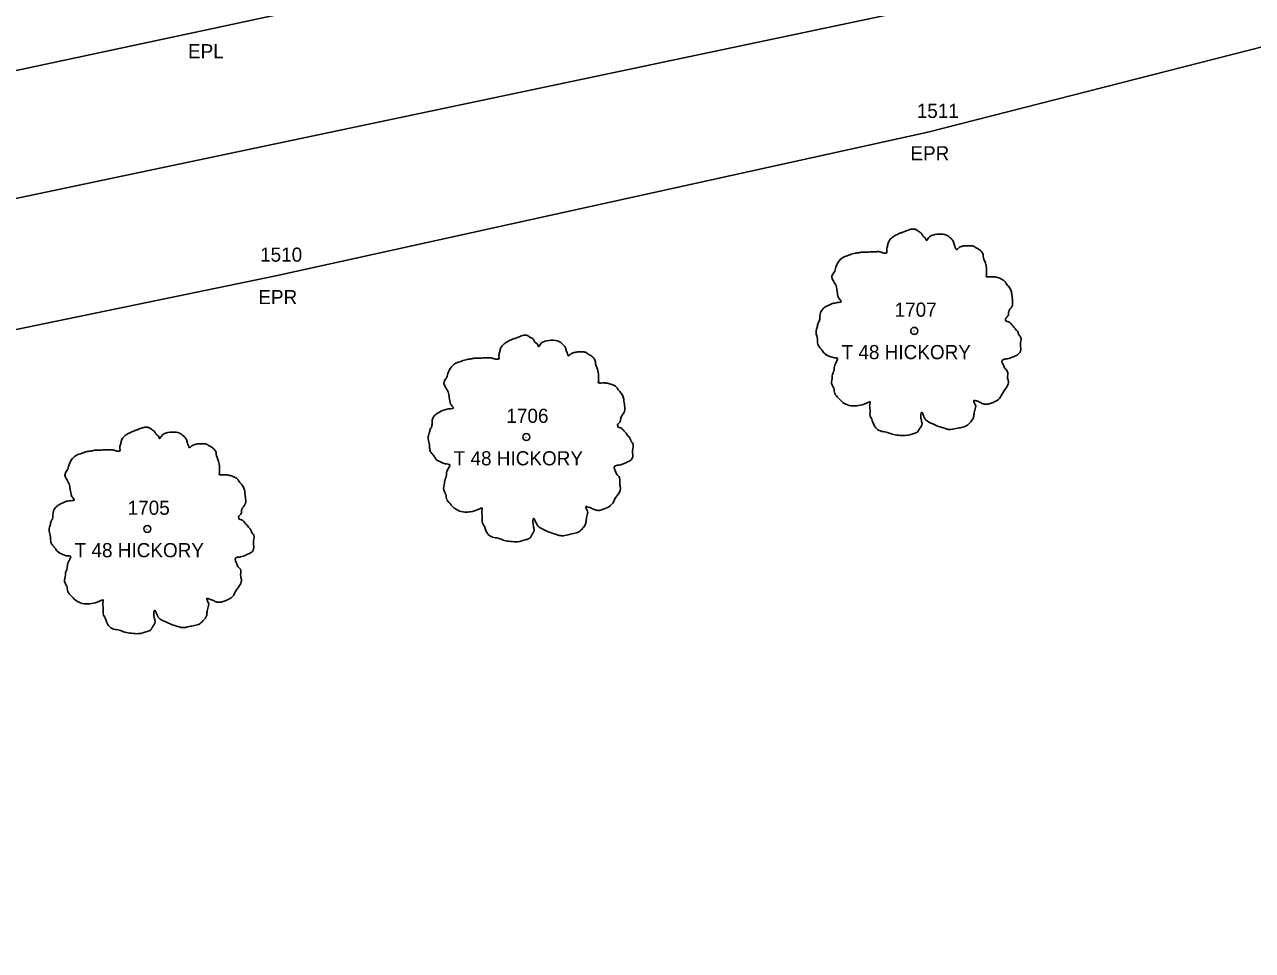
# Model space of a CAD drawing. Extents: x 1964982 to 1970452, y 1116335 to 1119906.
# Drawn here: x 1966611.8 to 1966698.6, y 1117353.3 to 1117418.7 of the extents above; entities that cross this region are included whole.
import ezdxf

# ---------------------------------------------------------------- set-up
doc = ezdxf.new("R2010")
doc.units = 0
for name, color, linetype in [('RD_EX_DV_Prop', 7, 'Continuous'), ('RD_EX_Road', 7, 'Continuous'), ('RD_EX_Road_txCode', 7, 'Continuous'), ('RD_EX_RW', 7, 'Continuous'), ('RD_EX_VEG', 7, 'Continuous'), ('RD_EX_VEG_txCode', 7, 'Continuous'), ('RD_HC_CL', 7, 'Continuous'), ('RD_SMD_Locator', 7, 'Continuous')]:
    doc.layers.add(name, color=color, linetype=linetype)

msp = doc.modelspace()

# ---------------------------------------------------------------- linework, layer by layer
at = {"layer": 'RD_EX_DV_Prop'}
msp.add_line((1966425.261, 1117367.215), (1966684.872, 1117421.945), dxfattribs=at)
at = {"layer": 'RD_EX_Road'}
for points in [[(1966484.547, 1117389.131), (1966531.199, 1117398.733), (1966578.388, 1117408.593), (1966604.527, 1117414.058), (1966624.537, 1117418.323), (1966671.319, 1117428.348), (1966716.506, 1117439.32), (1966736.604, 1117445.59), (1966754.133, 1117451.442), (1966759.658, 1117453.517), (1966769.512, 1117457.475)], [(1965729.992, 1117080.297), (1965819.77, 1117119.134), (1965907.737, 1117159.312), (1965995.365, 1117199.039), (1966039.268, 1117218.497), (1966081.241, 1117237.148), (1966124.665, 1117256.555), (1966167.659, 1117275.555), (1966211.467, 1117293.627), (1966257.791, 1117311.581), (1966302.7, 1117327.207), (1966347.903, 1117339.982), (1966394.806, 1117351.637), (1966441.557, 1117361.865), (1966488.625, 1117372.057), (1966534.906, 1117381.34), (1966581.234, 1117390.947), (1966629.533, 1117400.947), (1966675.632, 1117411.107), (1966721.676, 1117422.847), (1966766.802, 1117438.972), (1966775.751, 1117440.571)]]:
    msp.add_lwpolyline(points, dxfattribs=at)
at = {"layer": 'RD_EX_RW'}
for points in [[(1966484.547, 1117389.131), (1966531.199, 1117398.733), (1966578.388, 1117408.593), (1966604.527, 1117414.058), (1966624.537, 1117418.323), (1966671.319, 1117428.348), (1966716.506, 1117439.32), (1966736.604, 1117445.59), (1966754.133, 1117451.442), (1966759.658, 1117453.517), (1966769.512, 1117457.475)], [(1965729.992, 1117080.297), (1965819.77, 1117119.134), (1965907.737, 1117159.312), (1965995.365, 1117199.039), (1966039.268, 1117218.497), (1966081.241, 1117237.148), (1966124.665, 1117256.555), (1966167.659, 1117275.555), (1966211.467, 1117293.627), (1966257.791, 1117311.581), (1966302.7, 1117327.207), (1966347.903, 1117339.982), (1966394.806, 1117351.637), (1966441.557, 1117361.865), (1966488.625, 1117372.057), (1966534.906, 1117381.34), (1966581.234, 1117390.947), (1966629.533, 1117400.947), (1966675.632, 1117411.107), (1966721.676, 1117422.847), (1966766.802, 1117438.972), (1966775.751, 1117440.571)]]:
    msp.add_lwpolyline(points, dxfattribs=at)
at = {"layer": 'RD_EX_VEG'}
for centre, radius in [((1966674.675, 1117397.058), 0.25), ((1966674.662, 1117397.04), 0.0001), ((1966647.251, 1117389.554), 0.25), ((1966647.238, 1117389.535), 0.0001), ((1966620.454, 1117383.059), 0.25), ((1966620.441, 1117383.04), 0.0001)]:
    msp.add_circle(centre, radius, dxfattribs=at)
for points in [[(1966674.806, 1117404.226), (1966674.507, 1117404.251), (1966674.182, 1117404.151), (1966673.932, 1117404.051), (1966673.707, 1117403.976), (1966673.482, 1117403.876), (1966673.182, 1117403.701), (1966672.957, 1117403.501), (1966672.832, 1117403.251), (1966672.782, 1117403.026), (1966672.732, 1117402.751), (1966672.732, 1117402.576), (1966672.607, 1117402.551), (1966672.457, 1117402.576), (1966672.208, 1117402.651), (1966671.958, 1117402.651), (1966671.708, 1117402.651), (1966671.358, 1117402.626), (1966671.008, 1117402.626), (1966670.733, 1117402.576), (1966670.408, 1117402.526), (1966670.034, 1117402.401), (1966669.684, 1117402.276), (1966669.384, 1117402.027), (1966669.134, 1117401.552), (1966669.009, 1117401.202), (1966668.859, 1117400.952), (1966669.009, 1117400.502), (1966669.184, 1117400.152), (1966669.209, 1117399.952), (1966669.284, 1117399.528), (1966669.384, 1117399.303), (1966669.509, 1117399.103), (1966669.434, 1117399.078), (1966669.059, 1117399.028), (1966668.759, 1117398.928), (1966668.334, 1117398.703), (1966668.109, 1117398.478), (1966668.009, 1117398.153), (1966667.984, 1117397.803), (1966667.885, 1117397.604), (1966667.81, 1117397.329), (1966667.785, 1117397.254), (1966667.735, 1117396.929), (1966667.835, 1117396.479), (1966667.86, 1117396.129), (1966667.984, 1117395.904), (1966668.134, 1117395.729), (1966668.309, 1117395.479), (1966668.709, 1117395.255), (1966669.034, 1117395.155), (1966669.234, 1117395.13), (1966669.059, 1117394.63), (1966669.009, 1117394.28), (1966668.884, 1117393.88), (1966668.884, 1117393.805), (1966668.834, 1117393.33), (1966668.984, 1117393.005), (1966669.059, 1117392.631), (1966669.234, 1117392.406), (1966669.509, 1117392.106), (1966669.834, 1117391.881), (1966670.333, 1117391.756), (1966670.733, 1117391.781), (1966671.308, 1117391.956), (1966671.558, 1117392.031), (1966671.533, 1117391.856), (1966671.558, 1117391.481), (1966671.558, 1117391.056), (1966671.708, 1117390.732), (1966671.808, 1117390.457), (1966671.958, 1117390.207), (1966672.283, 1117389.982), (1966672.682, 1117389.907), (1966673.107, 1117389.757), (1966673.557, 1117389.682), (1966674.057, 1117389.657), (1966674.657, 1117389.807), (1966674.931, 1117389.932), (1966675.031, 1117390.107), (1966675.231, 1117390.482), (1966675.181, 1117390.707), (1966675.206, 1117391.306), (1966675.306, 1117391.131), (1966675.481, 1117390.781), (1966675.981, 1117390.482), (1966676.381, 1117390.307), (1966676.856, 1117390.157), (1966677.155, 1117390.082), (1966677.63, 1117390.157), (1966678.005, 1117390.232), (1966678.38, 1117390.357), (1966678.68, 1117390.632), (1966678.855, 1117390.906), (1966678.905, 1117391.181), (1966678.98, 1117391.556), (1966679.03, 1117391.731)], [(1966679.03, 1117391.731), (1966678.955, 1117391.906), (1966678.905, 1117392.156), (1966678.98, 1117392.131), (1966679.155, 1117392.081), (1966679.429, 1117391.956), (1966679.654, 1117391.881), (1966679.979, 1117391.906), (1966680.254, 1117392.006), (1966680.704, 1117392.281), (1966680.979, 1117392.756), (1966681.254, 1117393.155), (1966681.329, 1117393.48), (1966681.279, 1117393.705), (1966681.254, 1117394.205), (1966681.054, 1117394.455), (1966681.004, 1117394.58), (1966680.904, 1117394.98), (1966680.979, 1117395.03), (1966681.254, 1117395.08), (1966681.628, 1117395.205), (1966681.903, 1117395.329), (1966682.128, 1117395.504), (1966682.203, 1117395.729), (1966682.178, 1117396.129), (1966682.228, 1117396.529), (1966682.153, 1117396.679), (1966682.053, 1117396.829), (1966681.978, 1117397.029), (1966681.828, 1117397.179), (1966681.728, 1117397.329), (1966681.628, 1117397.429), (1966681.504, 1117397.579), (1966681.329, 1117397.703), (1966681.179, 1117397.753), (1966681.129, 1117397.903), (1966681.279, 1117398.103), (1966681.329, 1117398.203), (1966681.354, 1117398.428), (1966681.579, 1117398.778), (1966681.628, 1117399.178), (1966681.579, 1117399.603), (1966681.529, 1117399.878), (1966681.379, 1117400.152), (1966681.179, 1117400.402), (1966681.054, 1117400.577), (1966680.879, 1117400.702), (1966680.554, 1117400.827), (1966680.304, 1117400.877), (1966679.954, 1117400.877), (1966679.754, 1117400.927), (1966679.779, 1117400.977), (1966679.779, 1117401.127), (1966679.779, 1117401.402), (1966679.704, 1117401.852), (1966679.554, 1117402.351), (1966679.554, 1117402.376), (1966679.454, 1117402.626), (1966679.23, 1117402.826), (1966679.055, 1117402.926), (1966678.855, 1117403.051), (1966678.605, 1117403.076), (1966678.305, 1117403.076), (1966678.03, 1117403.026), (1966677.83, 1117402.926), (1966677.655, 1117402.801), (1966677.58, 1117402.951), (1966677.48, 1117403.251), (1966677.43, 1117403.401), (1966677.28, 1117403.576), (1966677.056, 1117403.776), (1966676.606, 1117403.901), (1966675.981, 1117403.826), (1966675.681, 1117403.626), (1966675.531, 1117403.451), (1966675.481, 1117403.576), (1966675.281, 1117403.776), (1966675.181, 1117403.951), (1966675.006, 1117404.076), (1966674.856, 1117404.176), (1966674.756, 1117404.226)], [(1966647.383, 1117396.721), (1966647.083, 1117396.746), (1966646.758, 1117396.646), (1966646.508, 1117396.546), (1966646.283, 1117396.471), (1966646.058, 1117396.371), (1966645.758, 1117396.196), (1966645.533, 1117395.996), (1966645.408, 1117395.746), (1966645.358, 1117395.522), (1966645.309, 1117395.247), (1966645.309, 1117395.072), (1966645.184, 1117395.047), (1966645.034, 1117395.072), (1966644.784, 1117395.147), (1966644.534, 1117395.147), (1966644.284, 1117395.147), (1966643.934, 1117395.122), (1966643.584, 1117395.122), (1966643.309, 1117395.072), (1966642.985, 1117395.022), (1966642.61, 1117394.897), (1966642.26, 1117394.772), (1966641.96, 1117394.522), (1966641.71, 1117394.047), (1966641.585, 1117393.697), (1966641.435, 1117393.447), (1966641.585, 1117392.998), (1966641.76, 1117392.648), (1966641.785, 1117392.448), (1966641.86, 1117392.023), (1966641.96, 1117391.798), (1966642.085, 1117391.598), (1966642.01, 1117391.573), (1966641.635, 1117391.523), (1966641.335, 1117391.423), (1966640.91, 1117391.198), (1966640.686, 1117390.974), (1966640.586, 1117390.649), (1966640.561, 1117390.299), (1966640.461, 1117390.099), (1966640.386, 1117389.824), (1966640.361, 1117389.749), (1966640.311, 1117389.424), (1966640.411, 1117388.974), (1966640.436, 1117388.625), (1966640.561, 1117388.4), (1966640.711, 1117388.225), (1966640.885, 1117387.975), (1966641.285, 1117387.75), (1966641.61, 1117387.65), (1966641.81, 1117387.625), (1966641.635, 1117387.125), (1966641.585, 1117386.775), (1966641.46, 1117386.376), (1966641.46, 1117386.301), (1966641.41, 1117385.826), (1966641.56, 1117385.501), (1966641.635, 1117385.126), (1966641.81, 1117384.901), (1966642.085, 1117384.601), (1966642.41, 1117384.376), (1966642.91, 1117384.251), (1966643.309, 1117384.276), (1966643.884, 1117384.451), (1966644.134, 1117384.526), (1966644.109, 1117384.351), (1966644.134, 1117383.977), (1966644.134, 1117383.552), (1966644.284, 1117383.227), (1966644.384, 1117382.952), (1966644.534, 1117382.702), (1966644.859, 1117382.477), (1966645.259, 1117382.402), (1966645.683, 1117382.252), (1966646.133, 1117382.177), (1966646.633, 1117382.152), (1966647.233, 1117382.302), (1966647.508, 1117382.427), (1966647.608, 1117382.602), (1966647.807, 1117382.977), (1966647.757, 1117383.202), (1966647.782, 1117383.802), (1966647.882, 1117383.627), (1966648.057, 1117383.277), (1966648.557, 1117382.977), (1966648.957, 1117382.802), (1966649.432, 1117382.652), (1966649.732, 1117382.577), (1966650.206, 1117382.652), (1966650.581, 1117382.727), (1966650.956, 1117382.852), (1966651.256, 1117383.127), (1966651.431, 1117383.402), (1966651.481, 1117383.677), (1966651.556, 1117384.052), (1966651.606, 1117384.226)], [(1966651.606, 1117384.226), (1966651.531, 1117384.401), (1966651.481, 1117384.651), (1966651.556, 1117384.626), (1966651.731, 1117384.576), (1966652.006, 1117384.451), (1966652.231, 1117384.376), (1966652.555, 1117384.401), (1966652.83, 1117384.501), (1966653.28, 1117384.776), (1966653.555, 1117385.251), (1966653.83, 1117385.651), (1966653.905, 1117385.976), (1966653.855, 1117386.201), (1966653.83, 1117386.7), (1966653.63, 1117386.95), (1966653.58, 1117387.075), (1966653.48, 1117387.475), (1966653.555, 1117387.525), (1966653.83, 1117387.575), (1966654.205, 1117387.7), (1966654.48, 1117387.825), (1966654.704, 1117388), (1966654.779, 1117388.225), (1966654.754, 1117388.625), (1966654.804, 1117389.024), (1966654.729, 1117389.174), (1966654.629, 1117389.324), (1966654.554, 1117389.524), (1966654.405, 1117389.674), (1966654.305, 1117389.824), (1966654.205, 1117389.924), (1966654.08, 1117390.074), (1966653.905, 1117390.199), (1966653.755, 1117390.249), (1966653.705, 1117390.399), (1966653.855, 1117390.599), (1966653.905, 1117390.699), (1966653.93, 1117390.924), (1966654.155, 1117391.273), (1966654.205, 1117391.673), (1966654.155, 1117392.098), (1966654.105, 1117392.373), (1966653.955, 1117392.648), (1966653.755, 1117392.898), (1966653.63, 1117393.073), (1966653.455, 1117393.198), (1966653.13, 1117393.323), (1966652.88, 1117393.372), (1966652.53, 1117393.372), (1966652.33, 1117393.422), (1966652.355, 1117393.472), (1966652.355, 1117393.622), (1966652.355, 1117393.897), (1966652.28, 1117394.347), (1966652.131, 1117394.847), (1966652.131, 1117394.872), (1966652.031, 1117395.122), (1966651.806, 1117395.322), (1966651.631, 1117395.422), (1966651.431, 1117395.547), (1966651.181, 1117395.572), (1966650.881, 1117395.572), (1966650.606, 1117395.522), (1966650.406, 1117395.422), (1966650.231, 1117395.297), (1966650.156, 1117395.447), (1966650.056, 1117395.746), (1966650.006, 1117395.896), (1966649.857, 1117396.071), (1966649.632, 1117396.271), (1966649.182, 1117396.396), (1966648.557, 1117396.321), (1966648.257, 1117396.121), (1966648.107, 1117395.946), (1966648.057, 1117396.071), (1966647.857, 1117396.271), (1966647.757, 1117396.446), (1966647.583, 1117396.571), (1966647.433, 1117396.671), (1966647.333, 1117396.721)], [(1966620.586, 1117390.226), (1966620.286, 1117390.251), (1966619.961, 1117390.151), (1966619.711, 1117390.052), (1966619.486, 1117389.977), (1966619.261, 1117389.877), (1966618.961, 1117389.702), (1966618.737, 1117389.502), (1966618.612, 1117389.252), (1966618.562, 1117389.027), (1966618.512, 1117388.752), (1966618.512, 1117388.577), (1966618.387, 1117388.552), (1966618.237, 1117388.577), (1966617.987, 1117388.652), (1966617.737, 1117388.652), (1966617.487, 1117388.652), (1966617.137, 1117388.627), (1966616.787, 1117388.627), (1966616.513, 1117388.577), (1966616.188, 1117388.527), (1966615.813, 1117388.402), (1966615.463, 1117388.277), (1966615.163, 1117388.027), (1966614.913, 1117387.553), (1966614.788, 1117387.203), (1966614.638, 1117386.953), (1966614.788, 1117386.503), (1966614.963, 1117386.153), (1966614.988, 1117385.953), (1966615.063, 1117385.529), (1966615.163, 1117385.304), (1966615.288, 1117385.104), (1966615.213, 1117385.079), (1966614.838, 1117385.029), (1966614.538, 1117384.929), (1966614.114, 1117384.704), (1966613.889, 1117384.479), (1966613.789, 1117384.154), (1966613.764, 1117383.804), (1966613.664, 1117383.604), (1966613.589, 1117383.329), (1966613.564, 1117383.254), (1966613.514, 1117382.93), (1966613.614, 1117382.48), (1966613.639, 1117382.13), (1966613.764, 1117381.905), (1966613.914, 1117381.73), (1966614.089, 1117381.48), (1966614.488, 1117381.255), (1966614.813, 1117381.155), (1966615.013, 1117381.13), (1966614.838, 1117380.631), (1966614.788, 1117380.281), (1966614.663, 1117379.881), (1966614.663, 1117379.806), (1966614.613, 1117379.331), (1966614.763, 1117379.006), (1966614.838, 1117378.632), (1966615.013, 1117378.407), (1966615.288, 1117378.107), (1966615.613, 1117377.882), (1966616.113, 1117377.757), (1966616.513, 1117377.782), (1966617.087, 1117377.957), (1966617.337, 1117378.032), (1966617.312, 1117377.857), (1966617.337, 1117377.482), (1966617.337, 1117377.057), (1966617.487, 1117376.732), (1966617.587, 1117376.457), (1966617.737, 1117376.208), (1966618.062, 1117375.983), (1966618.462, 1117375.908), (1966618.886, 1117375.758), (1966619.336, 1117375.683), (1966619.836, 1117375.658), (1966620.436, 1117375.808), (1966620.711, 1117375.933), (1966620.811, 1117376.108), (1966621.011, 1117376.482), (1966620.961, 1117376.707), (1966620.986, 1117377.307), (1966621.085, 1117377.132), (1966621.26, 1117376.782), (1966621.76, 1117376.482), (1966622.16, 1117376.308), (1966622.635, 1117376.158), (1966622.935, 1117376.083), (1966623.409, 1117376.158), (1966623.784, 1117376.233), (1966624.159, 1117376.358), (1966624.459, 1117376.632), (1966624.634, 1117376.907), (1966624.684, 1117377.182), (1966624.759, 1117377.557), (1966624.809, 1117377.732)], [(1966624.809, 1117377.732), (1966624.734, 1117377.907), (1966624.684, 1117378.157), (1966624.759, 1117378.132), (1966624.934, 1117378.082), (1966625.209, 1117377.957), (1966625.434, 1117377.882), (1966625.758, 1117377.907), (1966626.033, 1117378.007), (1966626.483, 1117378.282), (1966626.758, 1117378.756), (1966627.033, 1117379.156), (1966627.108, 1117379.481), (1966627.058, 1117379.706), (1966627.033, 1117380.206), (1966626.833, 1117380.456), (1966626.783, 1117380.581), (1966626.683, 1117380.98), (1966626.758, 1117381.03), (1966627.033, 1117381.08), (1966627.408, 1117381.205), (1966627.683, 1117381.33), (1966627.908, 1117381.505), (1966627.982, 1117381.73), (1966627.958, 1117382.13), (1966628.007, 1117382.53), (1966627.933, 1117382.68), (1966627.833, 1117382.83), (1966627.758, 1117383.03), (1966627.608, 1117383.179), (1966627.508, 1117383.329), (1966627.408, 1117383.429), (1966627.283, 1117383.579), (1966627.108, 1117383.704), (1966626.958, 1117383.754), (1966626.908, 1117383.904), (1966627.058, 1117384.104), (1966627.108, 1117384.204), (1966627.133, 1117384.429), (1966627.358, 1117384.779), (1966627.408, 1117385.179), (1966627.358, 1117385.603), (1966627.308, 1117385.878), (1966627.158, 1117386.153), (1966626.958, 1117386.403), (1966626.833, 1117386.578), (1966626.658, 1117386.703), (1966626.333, 1117386.828), (1966626.083, 1117386.878), (1966625.733, 1117386.878), (1966625.534, 1117386.928), (1966625.559, 1117386.978), (1966625.559, 1117387.128), (1966625.559, 1117387.403), (1966625.484, 1117387.852), (1966625.334, 1117388.352), (1966625.334, 1117388.377), (1966625.234, 1117388.627), (1966625.009, 1117388.827), (1966624.834, 1117388.927), (1966624.634, 1117389.052), (1966624.384, 1117389.077), (1966624.084, 1117389.077), (1966623.809, 1117389.027), (1966623.609, 1117388.927), (1966623.434, 1117388.802), (1966623.359, 1117388.952), (1966623.26, 1117389.252), (1966623.21, 1117389.402), (1966623.06, 1117389.577), (1966622.835, 1117389.777), (1966622.385, 1117389.902), (1966621.76, 1117389.827), (1966621.46, 1117389.627), (1966621.31, 1117389.452), (1966621.26, 1117389.577), (1966621.06, 1117389.777), (1966620.961, 1117389.952), (1966620.786, 1117390.077), (1966620.636, 1117390.176), (1966620.536, 1117390.226)]]:
    msp.add_spline(points, degree=3, dxfattribs=at)
at = {"layer": 'RD_HC_CL'}
msp.add_line((1966425.261, 1117367.215), (1966684.871, 1117421.945), dxfattribs=at)
at = {"layer": 'RD_SMD_Locator'}
for centre in [(1966624.537, 1117418.323), (1966624.537, 1117418.323), (1966675.632, 1117411.107), (1966675.632, 1117411.107), (1966629.533, 1117400.947), (1966629.533, 1117400.947)]:
    msp.add_circle(centre, 0.001, dxfattribs=at)

# ---------------------------------------------------------------- texts
at = {"layer": 'RD_EX_Road_txCode'}
for s, p in [('EPL', (1966623.332, 1117416.323)), ('EPL', (1966623.332, 1117416.323)), ('1511', (1966674.853, 1117412.107)), ('1511', (1966674.853, 1117412.107)), ('EPR', (1966674.404, 1117409.107)), ('EPR', (1966674.404, 1117409.107)), ('1510', (1966628.43, 1117401.947)), ('1510', (1966628.43, 1117401.947)), ('EPR', (1966628.304, 1117398.947)), ('EPR', (1966628.304, 1117398.947))]:
    msp.add_text(s, height=1, dxfattribs=at).set_placement(p)
at = {"layer": 'RD_EX_VEG_txCode'}
for s, p in [('1707', (1966673.289, 1117398.058)), ('T 48 HICKORY', (1966669.541, 1117395.058)), ('1706', (1966645.841, 1117390.554)), ('T 48 HICKORY', (1966642.117, 1117387.554)), ('1705', (1966619.068, 1117384.059)), ('T 48 HICKORY', (1966615.32, 1117381.059))]:
    msp.add_text(s, height=1, dxfattribs=at).set_placement(p)

doc.saveas('drawing.dxf')
